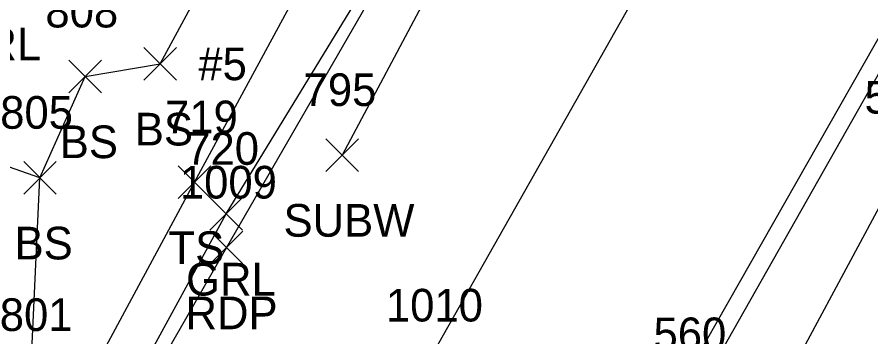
# Model space of a CAD drawing. Extents: x 1639430 to 1640195, y 612006 to 612917.
# Drawn here: x 1639797.2 to 1639849.6, y 612574.5 to 612594.1 of the extents above; entities that cross this region are included whole.
import ezdxf

# ---------------------------------------------------------------- set-up
doc = ezdxf.new("R2010")
doc.units = 0
for name, color, linetype in [('C_A', 7, 'Continuous'), ('L_A', 7, 'Continuous'), ('L_I', 7, 'Continuous'), ('L_TIC', 7, 'Continuous'), ('LELB', 7, 'Continuous'), ('P_A', 7, 'Continuous'), ('P_I', 7, 'Continuous'), ('P_TIC', 7, 'Continuous'), ('PET', 7, 'Continuous'), ('PRC', 7, 'Continuous'), ('R_A', 7, 'Continuous'), ('R_I', 7, 'Continuous'), ('R_TIC', 7, 'Continuous'), ('RGR', 7, 'Continuous'), ('U_A', 7, 'Continuous'), ('U_C', 7, 'Continuous'), ('U_I', 7, 'Continuous'), ('U_TIC', 7, 'Continuous'), ('UW', 7, 'Continuous')]:
    doc.layers.add(name, color=color, linetype=linetype)

msp = doc.modelspace()

# ---------------------------------------------------------------- linework, layer by layer
at = {"layer": 'L_TIC'}
for points in [[(1639805.01, 612590.217), (1639807.01, 612592.217)], [(1639807.01, 612590.217), (1639805.01, 612592.217)], [(1639800.408, 612589.442), (1639802.408, 612591.442)], [(1639802.408, 612589.442), (1639800.408, 612591.442)], [(1639797.637, 612583.242), (1639799.637, 612585.242)], [(1639799.637, 612583.242), (1639797.637, 612585.242)], [(1639797.637, 612583.242), (1639799.637, 612585.242)], [(1639799.637, 612583.242), (1639797.637, 612585.242)], [(1639807.106, 612582.963), (1639809.106, 612584.963)], [(1639809.106, 612582.963), (1639807.106, 612584.963)]]:
    msp.add_lwpolyline(points, dxfattribs=at)
at = {"layer": 'LELB'}
for points in [[(1639764.188, 612527.424), (1639772.977, 612544.039), (1639792.096, 612560.955), (1639798.045, 612571.861), (1639798.637, 612584.242), (1639801.408, 612590.442), (1639806.01, 612591.217), (1639813.347, 612604.755), (1639814.159, 612604.989), (1639815.502, 612605.955), (1639817.508, 612607.626), (1639823.926, 612612.002), (1639825.414, 612614.447), (1639825.954, 612618.423), (1639826.214, 612622.256), (1639826.372, 612626.105), (1639824.294, 612621.683), (1639822.313, 612620.482), (1639821.077, 612619.388), (1639821.02, 612619.326), (1639817.573, 612621.321), (1639806.603, 612624.212), (1639792.365, 612626.015), (1639770.728, 612640.749)], [(1639770.341, 612524.498), (1639771.372, 612528.696), (1639778.638, 612537.492), (1639795.972, 612561.5), (1639808.106, 612583.963), (1639817.63, 612601.539), (1639820.453, 612607.731), (1639824.84, 612610.698), (1639833.386, 612626.603), (1639829.018, 612631.624), (1639815.683, 612640.888)], [(1639873.784, 612630.158), (1639868.375, 612620.626), (1639857.45, 612600.97), (1639851.548, 612585.172), (1639842.168, 612567.758), (1639826.769, 612543.6), (1639823.114, 612538.523), (1639804.665, 612509.817), (1639793.927, 612486.538)], [(1639798.637, 612584.242), (1639790.638, 612587.031), (1639783.425, 612585.383), (1639768.307, 612566.176), (1639755.346, 612547.014), (1639737.305, 612513.749)]]:
    msp.add_lwpolyline(points, dxfattribs=at)
at = {"layer": 'P_TIC'}
for points in [[(1639809.07, 612578.968), (1639811.07, 612580.968)], [(1639811.07, 612578.968), (1639809.07, 612580.968)]]:
    msp.add_lwpolyline(points, dxfattribs=at)
at = {"layer": 'PET'}
for points in [[(1639860.191, 612668.905), (1639846.373, 612644.492), (1639830.054, 612614.558), (1639810.07, 612579.968), (1639792.174, 612548.775), (1639765.869, 612504.142)], [(1639889.959, 612664.779), (1639871.039, 612630.269), (1639855.317, 612602.067), (1639833.916, 612564.51), (1639815.495, 612533.184), (1639791.067, 612492.272)]]:
    msp.add_lwpolyline(points, dxfattribs=at)
at = {"layer": 'PRC'}
msp.add_lwpolyline([(1639858.802, 612637.722), (1639842.594, 612608.574), (1639822.132, 612572.441), (1639804.172, 612540.707), (1639777.378, 612495.693)], dxfattribs=at)
at = {"layer": 'R_TIC'}
for points in [[(1639809.049, 612581.033), (1639811.049, 612583.033)], [(1639811.049, 612581.033), (1639809.049, 612583.033)]]:
    msp.add_lwpolyline(points, dxfattribs=at)
at = {"layer": 'RGR'}
for points in [[(1639895.623, 612663.083), (1639891.964, 612661.302), (1639887.868, 612657.734), (1639885.714, 612654.678), (1639867.25, 612621.742), (1639856.032, 612601.171), (1639838.745, 612570.685), (1639824.789, 612544.939), (1639823.114, 612538.523), (1639823.733, 612532.824)], [(1639772.14, 612526.14), (1639776.867, 612528.109), (1639781.268, 612531.368), (1639783.057, 612534.432), (1639798.266, 612560.45), (1639810.049, 612582.033), (1639821.543, 612600.823), (1639833.331, 612621.737), (1639835.154, 612627.147), (1639835.455, 612631.126), (1639834.558, 612633.924)]]:
    msp.add_lwpolyline(points, dxfattribs=at)
at = {"layer": 'U_TIC'}
for points in [[(1639816.159, 612584.632), (1639818.159, 612586.632)], [(1639818.159, 612584.632), (1639816.159, 612586.632)]]:
    msp.add_lwpolyline(points, dxfattribs=at)
at = {"layer": 'UW'}
msp.add_lwpolyline([(1639878.262, 612694.255), (1639853.445, 612653.711), (1639817.159, 612585.632)], dxfattribs=at)

# ---------------------------------------------------------------- texts
at = {"layer": 'C_A'}
msp.add_text('HVCTRL', height=2, dxfattribs=at).set_placement((1639788.013, 612591.427))
at = {"layer": 'L_A'}
for s, p in [('BS', (1639804.45, 612586.217)), ('BS', (1639799.849, 612585.442)), ('BS', (1639797.078, 612579.242)), ('BS', (1639797.078, 612579.242)), ('TS', (1639806.515, 612578.963))]:
    msp.add_text(s, height=2, dxfattribs=at).set_placement(p)
at = {"layer": 'L_I'}
for s, p in [('808', (1639798.967, 612593.442)), ('558', (1639849.186, 612588.172)), ('805', (1639796.196, 612587.242)), ('805', (1639796.196, 612587.242)), ('719', (1639806.303, 612586.963)), ('801', (1639796.171, 612574.861)), ('801', (1639796.171, 612574.861))]:
    msp.add_text(s, height=2, dxfattribs=at).set_placement(p)
at = {"layer": 'P_A'}
msp.add_text('RDP', height=2, dxfattribs=at).set_placement((1639807.558, 612574.968))
at = {"layer": 'P_I'}
for s, p in [('1009', (1639807.212, 612582.968)), ('1010', (1639819.841, 612575.441))]:
    msp.add_text(s, height=2, dxfattribs=at).set_placement(p)
at = {"layer": 'R_A'}
msp.add_text('GRL', height=2, dxfattribs=at).set_placement((1639807.593, 612577.033))
at = {"layer": 'R_I'}
for s, p in [('720', (1639807.601, 612585.033)), ('560', (1639836.249, 612573.685))]:
    msp.add_text(s, height=2, dxfattribs=at).set_placement(p)
at = {"layer": 'U_A'}
msp.add_text('SUBW', height=2, dxfattribs=at).set_placement((1639813.568, 612580.632))
at = {"layer": 'U_C'}
msp.add_text('#5', height=2, dxfattribs=at).set_placement((1639808.343, 612590.214))
at = {"layer": 'U_I'}
msp.add_text('795', height=2, dxfattribs=at).set_placement((1639814.797, 612588.632))

doc.saveas('drawing.dxf')
